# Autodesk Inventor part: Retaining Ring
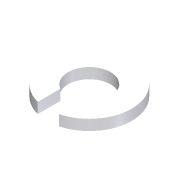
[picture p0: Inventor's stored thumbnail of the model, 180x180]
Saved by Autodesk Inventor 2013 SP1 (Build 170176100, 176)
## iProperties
Created: 2013-01
Part Number: Retaining Ring
Material: Aluminum 6061
Document SubType Name: Modeling
Designer: banachd
Density: 1 g/cm^3
Description: 2 mm RETAINING RING
Author: banachd
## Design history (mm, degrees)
sketch "Sketch1"
  geometry: L1 (-0.5, -0.866)-(-0.5, -1.936); L2 (0.5, -0.866)-(0.5, -1.936); A1 r 1 centre (0, 0) between (0.5, -0.866) and (-0.5, -0.866); A2 r 2 centre (0, 0) between (0.5, -1.936) and (-0.5, -1.936); 1 further point
  constraints: 4 end point, 4 point on circle, 2 centre point, 2 coincident, 2 vertical, 1 horizontal alignment
  dimensions: "d0" = 2 diameter of A1; "d1" = 4 diameter of A2; "d28" = 1 distance of L2.end L1.end
extrude "Extrusion1" new body sketch "Sketch1" distance "d29" = 0.5; taper "d30" = 0 deg
body "Solid1"
other parameters: "d13" = 18.5 [user parameter], "d14" = 4.45 [user parameter], "d15" = 0.67 [user parameter], "d16" = 2 [user parameter], "d17" = 2.68 [user parameter], "d18" = 8.5 [user parameter], "d19" = 11.2 [user parameter], "d20" = 2.5 [user parameter], "d21" = 4.5 [user parameter], "d22" = 14.5 [user parameter], "d23" = 6
